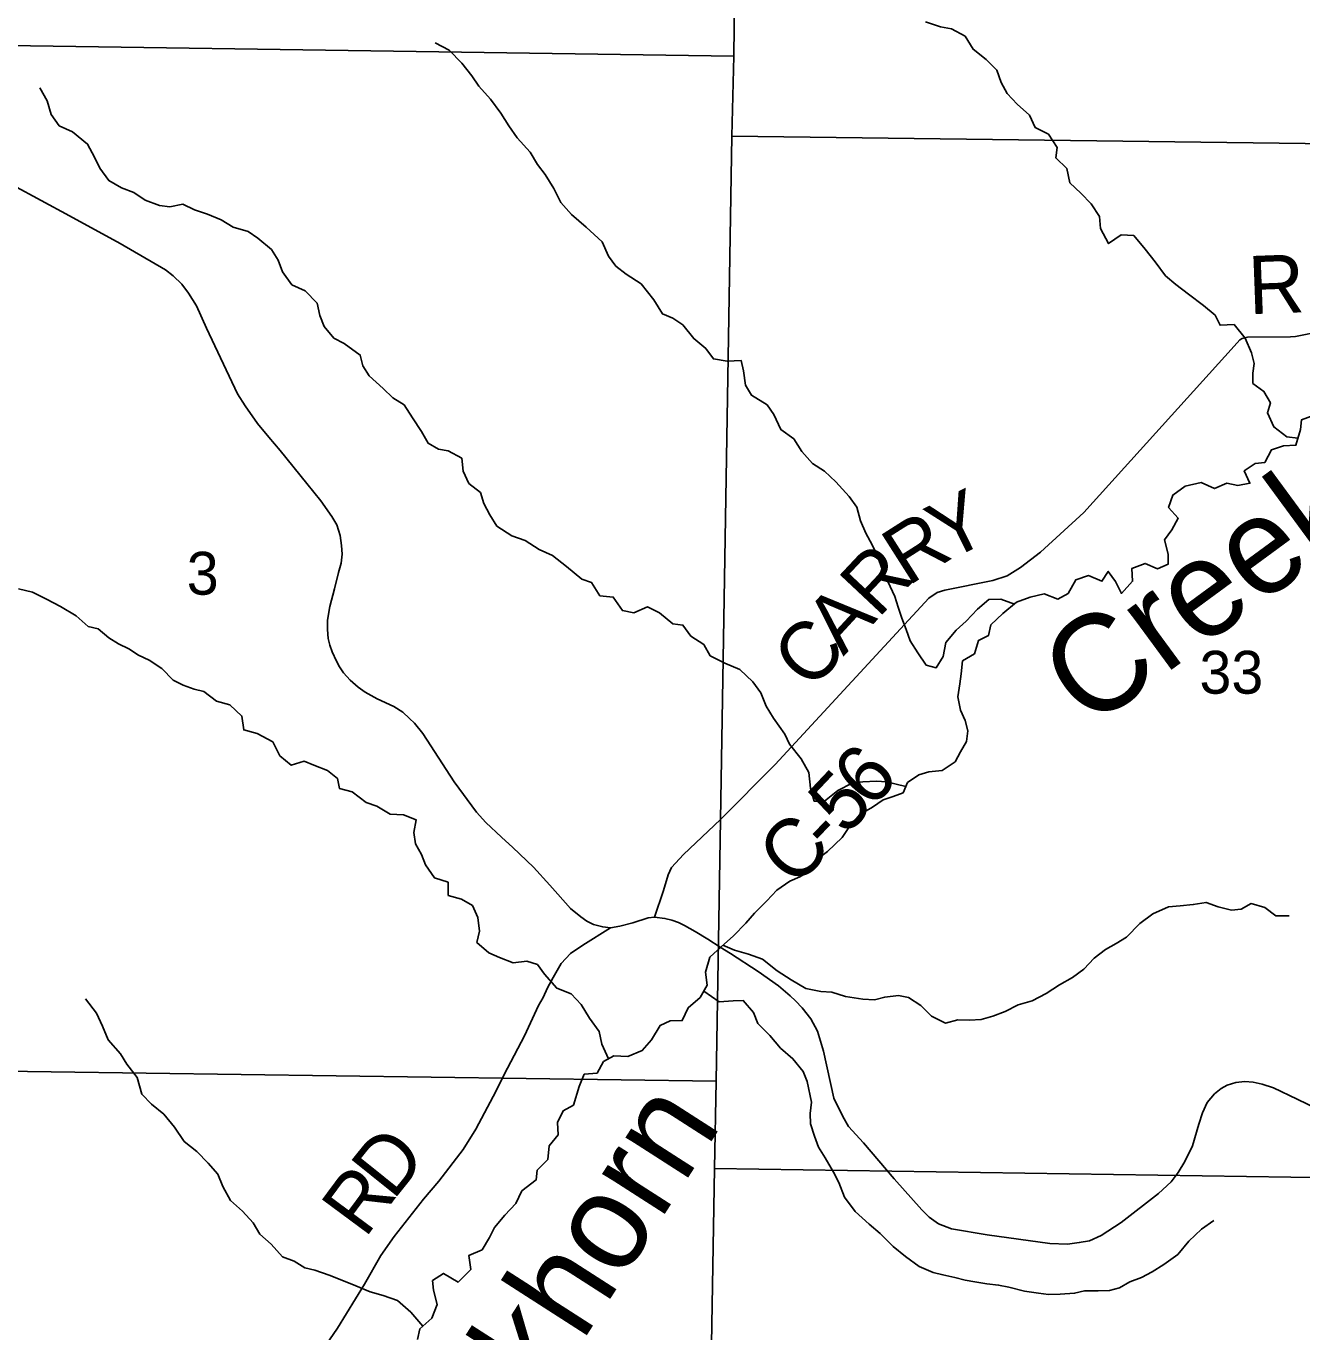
# Model space of a CAD drawing. Extents: x -3.6 to 34, y 0 to 32.8.
# Drawn here: x -0.41 to 0.835, y 30.853 to 32.129 of the extents above; entities that cross this region are included whole.
import ezdxf

# ---------------------------------------------------------------- set-up
doc = ezdxf.new("R2010")
doc.units = 0
for name, color, linetype in [('GM_X_Corporation', 7, 'Continuous'), ('GM_X_County_Road', 7, 'Continuous'), ('GM_X_County_Road_Text', 7, 'Continuous'), ('GM_X_Minor_River', 7, 'Continuous'), ('GM_X_Minor_River_Text', 7, 'Continuous'), ('GM_X_Section_Text', 7, 'Continuous'), ('GM_X_State_Route', 7, 'Continuous')]:
    doc.layers.add(name, color=color, linetype=linetype)

msp = doc.modelspace()

# ---------------------------------------------------------------- linework, layer by layer
at = {"layer": 'GM_X_Corporation'}
for points in [[(0.2894, 32.8429), (-0.7278, 32.8429), (-0.7385, 32.1141), (0.2807, 32.0992)], [(1.2753, 32.8429), (0.2894, 32.8429), (0.2807, 32.0992), (0.279, 32.0211), (1.2712, 32.0083)], [(0.2807, 32.0992), (0.279, 32.0211), (0.2635, 31.0982), (-0.7569, 31.1125), (-0.7385, 32.1141)], [(0.279, 32.0211), (1.2712, 32.0083), (1.2573, 30.9978), (0.262, 31.0128), (0.2635, 31.0982)], [(-0.7569, 31.1125), (0.2635, 31.0982), (0.262, 31.0128), (0.2459, 30.0789), (-0.7755, 30.0957)], [(0.262, 31.0128), (1.2573, 30.9978), (1.2483, 29.9822), (0.244, 29.9924), (0.2459, 30.0789)]]:
    msp.add_lwpolyline(points, close=True, dxfattribs=at)
at = {"layer": 'GM_X_County_Road'}
for points in [[(0.2032, 31.2583), (0.2122, 31.2842), (0.2168, 31.2995), (0.2201, 31.3068), (0.2317, 31.3195), (0.2679, 31.3537), (0.3213, 31.4072), (0.4711, 31.5698), (0.4794, 31.5753), (0.4869, 31.5777), (0.5336, 31.587), (0.5476, 31.5915), (0.5607, 31.5997), (0.5802, 31.6149), (0.6225, 31.6534), (0.7692, 31.8159), (0.7748, 31.8221), (0.7771, 31.8236), (0.7824, 31.8246), (0.8243, 31.825), (0.8292, 31.8255), (0.855, 31.8306)], [(-0.136, 30.813), (-0.1061, 30.8567), (-0.0798, 30.8999), (-0.0638, 30.9277), (-0.0508, 30.9463), (-0.0221, 30.9828), (-0.0072, 31.0003), (0.0167, 31.0312), (0.0288, 31.051), (0.0457, 31.083), (0.0599, 31.1106), (0.0764, 31.1422), (0.09, 31.172), (0.0945, 31.1797), (0.099, 31.1892), (0.1044, 31.1993), (0.1122, 31.213), (0.1215, 31.2226), (0.1334, 31.2309), (0.1605, 31.2478)], [(0.1605, 31.2478), (0.1695, 31.2494), (0.1823, 31.2526), (0.1972, 31.2575), (0.2032, 31.2583)]]:
    msp.add_lwpolyline(points, dxfattribs=at)
at = {"layer": 'GM_X_Minor_River'}
for points in [[(0.8315, 31.726), (0.8207, 31.7274), (0.808, 31.7371), (0.8017, 31.751), (0.8046, 31.7605), (0.7983, 31.7718), (0.7876, 31.7796), (0.7874, 31.7895), (0.7887, 31.799), (0.7863, 31.8095), (0.78, 31.8239), (0.7691, 31.837), (0.7555, 31.8364), (0.7507, 31.8461), (0.7392, 31.8558), (0.7246, 31.8669), (0.7123, 31.8762), (0.7023, 31.8848), (0.6922, 31.8983), (0.6825, 31.9106), (0.6712, 31.9241), (0.6591, 31.9247), (0.6467, 31.9161), (0.6388, 31.9308), (0.6379, 31.9425), (0.6297, 31.9549), (0.6196, 31.9654), (0.6089, 31.9754), (0.606, 31.9894), (0.5951, 31.9999), (0.5965, 32.0101), (0.5879, 32.0229), (0.5749, 32.0295), (0.5694, 32.0416), (0.5574, 32.0524), (0.5478, 32.0628), (0.5419, 32.0734), (0.5375, 32.0854), (0.5271, 32.0959), (0.5144, 32.1059), (0.5066, 32.1187), (0.4932, 32.126), (0.4825, 32.1278), (0.468, 32.1328)], [(0.5547, 31.5641), (0.5413, 31.5687), (0.5299, 31.5685), (0.5186, 31.5592), (0.5075, 31.5473), (0.4977, 31.5384), (0.4877, 31.5265), (0.4853, 31.5128), (0.4782, 31.5017), (0.4687, 31.5045), (0.4605, 31.5165), (0.4531, 31.5282), (0.4491, 31.5391), (0.4448, 31.5504), (0.4412, 31.561), (0.4379, 31.5716), (0.4312, 31.5862), (0.4261, 31.5972), (0.421, 31.6107), (0.4158, 31.622), (0.4096, 31.6333), (0.4044, 31.6454), (0.4008, 31.6586), (0.3934, 31.6691), (0.3803, 31.6833), (0.3694, 31.6937), (0.3575, 31.7015), (0.3471, 31.7131), (0.3393, 31.7255), (0.3266, 31.7344), (0.3199, 31.7491), (0.3133, 31.7588), (0.298, 31.768), (0.2921, 31.7778), (0.2903, 31.7918), (0.2879, 31.802), (0.2742, 31.8014), (0.2609, 31.8035), (0.2535, 31.8136), (0.2416, 31.8233), (0.2311, 31.8367), (0.2211, 31.8434), (0.2112, 31.8474), (0.2026, 31.8613), (0.1902, 31.877), (0.1756, 31.8863), (0.1656, 31.8941), (0.1586, 31.9038), (0.1523, 31.9178), (0.1365, 31.9323), (0.1222, 31.9446), (0.1118, 31.9562), (0.1051, 31.9701), (0.0965, 31.9836), (0.0891, 31.9934), (0.0821, 32.0054), (0.0693, 32.0196), (0.0612, 32.0312), (0.0534, 32.0436), (0.0433, 32.0571), (0.0317, 32.0698), (0.025, 32.0799), (0.0153, 32.0923), (0.003, 32.105), (-0.0108, 32.1124)], [(0.4487, 31.3857), (0.43, 31.3904), (0.4201, 31.391), (0.4068, 31.3904), (0.3962, 31.3891), (0.3823, 31.3821), (0.3692, 31.3716), (0.3593, 31.3714), (0.3557, 31.3843), (0.3539, 31.3994), (0.3464, 31.413), (0.3352, 31.4272), (0.3305, 31.437), (0.3196, 31.4527), (0.3125, 31.4644), (0.307, 31.4772), (0.2992, 31.4881), (0.2865, 31.5), (0.272, 31.5062), (0.2578, 31.5136), (0.2515, 31.5244), (0.2389, 31.5326), (0.2311, 31.5435), (0.2212, 31.5448), (0.2081, 31.5556), (0.1966, 31.5615), (0.1831, 31.5556), (0.172, 31.5577), (0.1631, 31.5708), (0.1501, 31.5721), (0.1419, 31.5852), (0.1324, 31.5885), (0.1174, 31.6008), (0.1039, 31.6115), (0.0909, 31.6174), (0.0771, 31.6263), (0.0641, 31.6306), (0.0495, 31.6402), (0.0425, 31.6511), (0.0366, 31.6624), (0.0334, 31.673), (0.0222, 31.6819), (0.0167, 31.6939), (0.0154, 31.7064), (0.002, 31.7138), (-0.0076, 31.7155), (-0.0175, 31.7211), (-0.0242, 31.7327), (-0.0328, 31.7459), (-0.0409, 31.7586), (-0.0521, 31.7656), (-0.0617, 31.7746), (-0.0752, 31.7869), (-0.0815, 31.7966), (-0.0839, 31.8072), (-0.0997, 31.8187), (-0.1096, 31.8239), (-0.1193, 31.8351), (-0.1233, 31.846), (-0.1261, 31.8581), (-0.1377, 31.8701), (-0.1507, 31.8759), (-0.1597, 31.8887), (-0.1641, 31.9), (-0.1707, 31.9105), (-0.1838, 31.9213), (-0.1934, 31.928), (-0.2079, 31.9323), (-0.2198, 31.9393), (-0.2332, 31.9448), (-0.2458, 31.9491), (-0.2572, 31.9546), (-0.2697, 31.9521), (-0.28, 31.9535), (-0.2938, 31.9585), (-0.3049, 31.9659), (-0.3171, 31.9707), (-0.3294, 31.9777), (-0.3383, 31.9897), (-0.3434, 32.0006), (-0.3501, 32.0134), (-0.3647, 32.0253), (-0.3778, 32.0311), (-0.3855, 32.0424), (-0.3896, 32.0556), (-0.3966, 32.0684)], [(0.1297, 31.0929), (0.1348, 31.1048), (0.1473, 31.1057), (0.1536, 31.1172), (0.1638, 31.1227), (0.1774, 31.1222), (0.1914, 31.1281), (0.2003, 31.1385), (0.2088, 31.1523), (0.2186, 31.157), (0.2304, 31.1572), (0.2362, 31.1698), (0.2478, 31.1799), (0.2549, 31.1918), (0.2531, 31.2046), (0.2574, 31.2191), (0.2683, 31.2292), (0.2806, 31.24), (0.2926, 31.2523), (0.3011, 31.262), (0.3131, 31.2743), (0.3228, 31.2847), (0.3355, 31.2933), (0.3453, 31.2976), (0.3555, 31.3038), (0.361, 31.3138), (0.3723, 31.3223), (0.3865, 31.3362), (0.3931, 31.3458), (0.4039, 31.3585), (0.4163, 31.3656), (0.4265, 31.3729), (0.4363, 31.3761), (0.4461, 31.3797), (0.4505, 31.3897), (0.4614, 31.3974), (0.4712, 31.4002), (0.4841, 31.4016), (0.4968, 31.4101), (0.502, 31.4197), (0.5079, 31.4297), (0.5092, 31.4403), (0.5068, 31.4502), (0.5021, 31.4603), (0.4996, 31.4736), (0.5013, 31.4861), (0.5026, 31.496), (0.5039, 31.5085), (0.5156, 31.5156), (0.5195, 31.5285), (0.5293, 31.5332), (0.5318, 31.5439), (0.5434, 31.5547), (0.5569, 31.5659), (0.5701, 31.5707), (0.5837, 31.574), (0.5971, 31.5689), (0.6072, 31.5744), (0.6146, 31.5878), (0.6271, 31.5918), (0.6401, 31.5863), (0.6464, 31.5959), (0.6534, 31.5861), (0.6592, 31.5745), (0.6701, 31.5864), (0.6695, 31.5989), (0.6823, 31.6037), (0.6945, 31.5986), (0.7047, 31.6029), (0.7049, 31.6128), (0.7013, 31.6268), (0.7083, 31.6364), (0.7146, 31.6479), (0.7053, 31.6583), (0.7093, 31.6705), (0.7213, 31.6791), (0.7372, 31.6828), (0.7502, 31.6769), (0.7622, 31.682), (0.7729, 31.6799), (0.7846, 31.682), (0.7791, 31.6941), (0.7896, 31.7015), (0.7991, 31.7024), (0.8057, 31.7146), (0.8174, 31.7186), (0.8296, 31.7192), (0.8339, 31.7345), (0.8349, 31.744), (0.8473, 31.7487)], [(0.1586, 31.1199), (0.1518, 31.1343), (0.1493, 31.1464), (0.14, 31.1595), (0.1318, 31.173), (0.1221, 31.1835), (0.108, 31.1889), (0.096, 31.2024), (0.089, 31.2121), (0.0787, 31.2154), (0.0654, 31.2137), (0.052, 31.2187), (0.0417, 31.2235), (0.0298, 31.2335), (0.0326, 31.2446), (0.0309, 31.2579), (0.0257, 31.2695), (0.015, 31.2758), (0.002, 31.2794), (0.0018, 31.2923), (-0.0115, 31.2966), (-0.0201, 31.3094), (-0.0241, 31.3195), (-0.0299, 31.3297), (-0.0317, 31.341), (-0.0292, 31.3532), (-0.0418, 31.3583), (-0.0547, 31.3589), (-0.0678, 31.3666), (-0.0781, 31.3702), (-0.0919, 31.3806), (-0.1041, 31.3838), (-0.1062, 31.3937), (-0.1158, 31.4015), (-0.1292, 31.4066), (-0.1388, 31.4106), (-0.1512, 31.4066), (-0.1624, 31.4159), (-0.1694, 31.4294), (-0.1844, 31.4375), (-0.1977, 31.4411), (-0.1995, 31.4547), (-0.2111, 31.4655), (-0.2244, 31.4691), (-0.2367, 31.4788), (-0.2462, 31.4809), (-0.2569, 31.4849), (-0.2665, 31.4897), (-0.2777, 31.5012), (-0.29, 31.5094), (-0.3003, 31.5141), (-0.3099, 31.5204), (-0.3199, 31.5252), (-0.3295, 31.5311), (-0.3399, 31.54), (-0.3494, 31.5422), (-0.3614, 31.5526), (-0.3767, 31.5618), (-0.3901, 31.5688), (-0.4039, 31.5758), (-0.4176, 31.579)], [(0.2702, 31.2309), (0.2816, 31.226), (0.295, 31.222), (0.3087, 31.2173), (0.323, 31.2058), (0.3368, 31.1969), (0.351, 31.1884), (0.3658, 31.1856), (0.3765, 31.1851), (0.3898, 31.1807), (0.4066, 31.178), (0.418, 31.1774), (0.4282, 31.1802), (0.4415, 31.1816), (0.4514, 31.1799), (0.4633, 31.1721), (0.4737, 31.1616), (0.4875, 31.1547), (0.4996, 31.1579), (0.511, 31.1577), (0.5223, 31.1583), (0.5337, 31.1615), (0.5457, 31.1662), (0.5585, 31.1725), (0.5721, 31.1765), (0.5857, 31.1836), (0.5988, 31.1922), (0.6113, 31.1992), (0.6225, 31.2074), (0.6326, 31.2181), (0.6438, 31.2267), (0.654, 31.2325), (0.6641, 31.2388), (0.6772, 31.2519), (0.6899, 31.2616), (0.705, 31.2683), (0.7164, 31.2692), (0.7293, 31.2706), (0.7418, 31.2727), (0.7536, 31.2683), (0.7666, 31.2651), (0.7761, 31.2661), (0.7858, 31.2715), (0.7992, 31.2676), (0.81, 31.2594), (0.8229, 31.2596)], [(0.2515, 31.186), (0.2665, 31.1756), (0.2802, 31.1766), (0.29, 31.1768), (0.3001, 31.1652), (0.3041, 31.1543), (0.3161, 31.1427), (0.3265, 31.1304), (0.3385, 31.1199), (0.3485, 31.1076), (0.3525, 31.0978)], [(-0.2973, 31.0855), (-0.3018, 31.1017), (-0.3119, 31.1148), (-0.3181, 31.1249), (-0.3301, 31.1384), (-0.3356, 31.1516), (-0.3415, 31.1644), (-0.352, 31.1786)], [(0.3525, 31.0978), (0.3567, 31.0774), (0.3554, 31.0664), (0.3555, 31.0565), (0.3595, 31.0444), (0.3634, 31.0335), (0.37, 31.023), (0.3782, 31.0091), (0.3833, 30.9989), (0.3888, 30.9846), (0.3992, 30.9707), (0.413, 30.9584), (0.4238, 30.9494), (0.4364, 30.9367), (0.4483, 30.9267), (0.4617, 30.917), (0.4754, 30.9112), (0.4849, 30.909), (0.4967, 30.9062), (0.5066, 30.9037), (0.5161, 30.9019), (0.5278, 30.9002), (0.5392, 30.8989), (0.5494, 30.8967), (0.5646, 30.8928), (0.5783, 30.8911), (0.5881, 30.8897), (0.5995, 30.8899), (0.6135, 30.8909), (0.6233, 30.8933), (0.6365, 30.8931), (0.6475, 30.8937), (0.6573, 30.8961), (0.6674, 30.902), (0.6787, 30.9063), (0.6892, 30.9118), (0.7005, 30.9191), (0.7143, 30.9288), (0.7251, 30.9419), (0.7374, 30.9535), (0.7494, 30.962)], [(-0.0229, 30.8587), (-0.0344, 30.8723), (-0.0475, 30.8838), (-0.0616, 30.8886), (-0.0741, 30.8922), (-0.0882, 30.898), (-0.1034, 30.9042), (-0.1141, 30.9086), (-0.1282, 30.9133), (-0.138, 30.9158), (-0.1484, 30.9221), (-0.1598, 30.9265), (-0.1709, 30.9389), (-0.1821, 30.9485), (-0.1883, 30.9598), (-0.199, 30.971), (-0.2106, 30.9815), (-0.218, 30.995), (-0.2231, 31.0071), (-0.2323, 31.018), (-0.2435, 31.0295), (-0.2557, 31.0392), (-0.2654, 31.0531), (-0.2758, 31.0658), (-0.2877, 31.0755), (-0.2973, 31.0855)], [(-0.028, 30.8458), (-0.0259, 30.8561), (-0.0139, 30.8665), (-0.0088, 30.8799), (-0.0124, 30.8939), (-0.0134, 30.9033), (-0.0025, 30.9103), (0.0116, 30.9018), (0.0239, 30.9141), (0.0222, 30.9278), (0.035, 30.9333), (0.0424, 30.9455), (0.0472, 30.9551), (0.0572, 30.967), (0.068, 30.9785), (0.0739, 30.9908), (0.0877, 31.0016), (0.0887, 31.0111), (0.0991, 31.0215), (0.1004, 31.0348), (0.1093, 31.0455), (0.1088, 31.0577), (0.1143, 31.0691), (0.1244, 31.0746), (0.1297, 31.0929)]]:
    msp.add_lwpolyline(points, dxfattribs=at)
at = {"layer": 'GM_X_State_Route'}
for points in [[(0.1605, 31.2478), (0.1529, 31.2487), (0.1438, 31.2512), (0.1373, 31.2543), (0.1313, 31.2585), (0.1214, 31.2667), (0.1089, 31.2807), (0.1012, 31.2895), (0.0852, 31.3071), (0.0651, 31.3264), (0.0541, 31.3364), (0.0386, 31.3507), (0.0297, 31.3608), (0.0078, 31.3904), (-0.0229, 31.4377), (-0.031, 31.4478), (-0.0359, 31.4523), (-0.0425, 31.4585), (-0.0511, 31.4639), (-0.0673, 31.4716), (-0.0791, 31.4781), (-0.0858, 31.4829), (-0.0937, 31.4897), (-0.1002, 31.497), (-0.1041, 31.5029), (-0.107, 31.5082), (-0.1112, 31.5174), (-0.1135, 31.524), (-0.1151, 31.5304), (-0.1159, 31.5391), (-0.1159, 31.5482), (-0.1137, 31.5616), (-0.1089, 31.579), (-0.1051, 31.595), (-0.1025, 31.6039), (-0.1017, 31.6128), (-0.1022, 31.6214), (-0.1035, 31.6309), (-0.1069, 31.6415), (-0.1115, 31.6495), (-0.1223, 31.665), (-0.1361, 31.6818), (-0.162, 31.7139), (-0.1733, 31.7271), (-0.1842, 31.7405), (-0.1964, 31.7578), (-0.2036, 31.7694), (-0.2339, 31.8335), (-0.2439, 31.8552), (-0.2516, 31.8678), (-0.258, 31.8764), (-0.2667, 31.8847), (-0.2742, 31.8906), (-0.3184, 31.9164), (-0.3678, 31.9432), (-0.4231, 31.9732)], [(0.2032, 31.2583), (0.1972, 31.2575), (0.1823, 31.2526), (0.1695, 31.2494), (0.1605, 31.2478)], [(0.8598, 31.0666), (0.8306, 31.0803), (0.8075, 31.0914), (0.7967, 31.0951), (0.7877, 31.0971), (0.7797, 31.0978), (0.7709, 31.0967), (0.7623, 31.094), (0.7567, 31.091), (0.7502, 31.0856), (0.743, 31.0773), (0.7382, 31.067), (0.7349, 31.0561), (0.7286, 31.035), (0.721, 31.0195), (0.7147, 31.0088), (0.7077, 30.9997), (0.6953, 30.9884), (0.659, 30.9599), (0.6393, 30.9473), (0.6279, 30.9422), (0.618, 30.9403), (0.6066, 30.9388), (0.5894, 30.9396), (0.5281, 30.948), (0.4933, 30.9538), (0.4807, 30.9587), (0.4715, 30.9652), (0.4644, 30.9724), (0.4372, 31.0025), (0.4074, 31.0379), (0.3928, 31.0536), (0.3873, 31.0636), (0.3785, 31.0814), (0.3685, 31.1272), (0.3624, 31.1468), (0.3559, 31.1588), (0.3476, 31.1696), (0.3409, 31.1766), (0.3358, 31.1815), (0.3245, 31.1912), (0.3047, 31.2051), (0.2774, 31.2228), (0.2676, 31.229), (0.2554, 31.2369), (0.2432, 31.2443), (0.2326, 31.2502), (0.2269, 31.2531), (0.2202, 31.2553), (0.2135, 31.257), (0.2032, 31.2583)]]:
    msp.add_lwpolyline(points, dxfattribs=at)

# ---------------------------------------------------------------- texts
at = {"layer": 'GM_X_County_Road_Text'}
for s, rotation, p in [('R', 2.1276, (0.7839, 31.8471)), ('Y', 26.3337, (0.4885, 31.6051)), ('R', 32.4365, (0.4505, 31.5809)), ('R', 46.7914, (0.4215, 31.5492)), ('A', 47.3227, (0.3877, 31.5126)), ('C', 47.3285, (0.356, 31.4783)), ('6', 47.4457, (0.4148, 31.3629)), ('5', 46.6252, (0.3901, 31.3368)), ('C', 45.1118, (0.3398, 31.2858)), ('-', 45.8327, (0.3733, 31.3195)), ('D', 51.2446, (-0.0519, 30.9807)), ('R', 53.4509, (-0.0793, 30.9436))]:
    msp.add_text(s, height=0.0568, rotation=rotation, dxfattribs=at).set_placement(p)
at = {"layer": 'GM_X_Minor_River_Text'}
for s, height, rotation, p in [('Creek', 0.0947, 36.301, (0.6273, 31.4405)), ('Elkhorn', 0.09469, 57.285, (0.0375, 30.6945))]:
    msp.add_text(s, height=height, rotation=rotation, dxfattribs=at).set_placement(p)
at = {"layer": 'GM_X_Section_Text'}
for s, height, p in [('3', 0.0419, (-0.2533, 31.5732)), ('33', 0.04186, (0.7354, 31.4765))]:
    msp.add_text(s, height=height, rotation=0, dxfattribs=at).set_placement(p)

doc.saveas('drawing.dxf')
